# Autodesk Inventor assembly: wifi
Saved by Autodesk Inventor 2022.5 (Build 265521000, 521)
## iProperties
Created: 2024-12
Part Number: wifi
Document SubType Name: Assembly
Designer: AdminForWorker
Title: wifi
Author: AdminForWorker
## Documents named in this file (2)
- c:\worker\convert-fusion-r05-cosv3\tmp\job-1\35\temp\files\545dca92-a972-481a-9197-dd1a1176500e\wifi.iam
- c:\worker\convert-fusion-r05-cosv3\tmp\job-1\35\temp\files\545dca92-a972-481a-9197-dd1a1176500e\Component73.ipt
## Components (1 placed, 1 different names)
1. Component73:1
